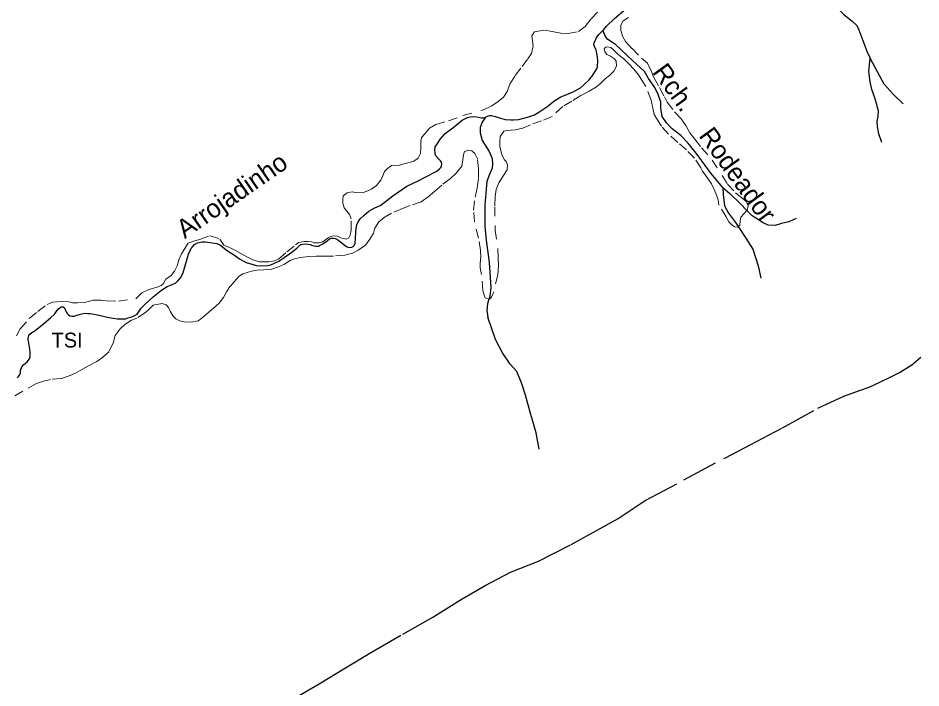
# Model space of a CAD drawing. Extents: x 391.8 to 446, y 8452 to 8507.5.
# Drawn here: x 436.28 to 445.98, y 8458.87 to 8466.06 of the extents above; entities that cross this region are included whole.
import ezdxf
from ezdxf.enums import TextEntityAlignment as Align

# ---------------------------------------------------------------- set-up
doc = ezdxf.new("R2010")
doc.units = 0
doc.header["$LTSCALE"] = 0.064
doc.linetypes.add('LONG_DASHED', pattern=[7.5, 6, -1.5])
doc.linetypes.add('SHORT_DASHED', pattern=[2.7, 1.5, -1.2])
for name, color, linetype, lineweight in [('21', 7, 'SHORT_DASHED', 13), ('7', 7, 'Continuous', 25), ('9', 7, 'LONG_DASHED', 25)]:
    doc.layers.add(name, color=color, linetype=linetype, lineweight=lineweight)
doc.layers.add('61', color=7, linetype='Continuous')

msp = doc.modelspace()

# ---------------------------------------------------------------- linework, layer by layer
at = {"layer": '21'}
for points in [[(440.4417, 8464.5019), (440.5309, 8464.5279), (440.5793, 8464.5613), (440.6053, 8464.6096), (440.609, 8464.6727), (440.609, 8464.7358), (440.6164, 8464.7803), (440.6499, 8464.8212), (440.7019, 8464.8806), (440.7696, 8464.9199), (440.9034, 8464.9607), (441.0595, 8465.0164), (441.2826, 8465.0795), (441.3718, 8465.1204), (441.4387, 8465.1686), (441.4944, 8465.2132), (441.5353, 8465.2763), (441.5651, 8465.3542), (441.6208, 8465.447), (441.6952, 8465.5436), (441.7556, 8465.6272), (441.7965, 8465.6829), (441.8151, 8465.7646), (441.8077, 8465.8202), (441.8002, 8465.8722), (441.83, 8465.9168), (441.9378, 8465.9353), (442.0196, 8465.9205), (442.1125, 8465.9019), (442.1905, 8465.8982), (442.3021, 8465.9205), (442.3727, 8465.9724), (442.4359, 8466.0578), (442.5065, 8466.1284)], [(442.8392, 8466.0715), (442.7798, 8466.0344), (442.7575, 8465.9898), (442.7575, 8465.9304), (442.776, 8465.8636), (442.8058, 8465.8116), (442.8764, 8465.7374), (442.9768, 8465.6334), (443.0437, 8465.5815), (443.0808, 8465.4961), (443.1106, 8465.4255), (443.1701, 8465.3179), (443.2258, 8465.2176), (443.2523, 8465.1599), (443.3341, 8465.056), (443.4047, 8464.9817), (443.453, 8464.9112), (443.4976, 8464.8333), (443.5497, 8464.7627), (443.624, 8464.6699), (443.7355, 8464.54), (443.9033, 8464.2814), (443.9888, 8464.1886), (444.0557, 8464.1329), (444.1041, 8464.092), (444.1226, 8464.0475), (444.1115, 8463.9992), (444.1104, 8463.998)], [(444.016, 8463.8247), (444.0074, 8463.8173), (443.9777, 8463.821), (443.9517, 8463.8396), (443.9145, 8463.8767), (443.8885, 8463.9287), (443.81, 8464.0563), (443.8025, 8464.112), (443.7802, 8464.1751), (443.7579, 8464.2233), (443.7282, 8464.2827), (443.691, 8464.3421), (443.6315, 8464.4201), (443.6166, 8464.4551), (443.546, 8464.5591), (443.4605, 8464.6482), (443.3676, 8464.7298), (443.2672, 8464.8189), (443.1929, 8464.9043), (443.152, 8464.9637), (443.1148, 8465.0305), (443.0999, 8465.0973), (443.0813, 8465.1827), (443.0245, 8465.3293), (442.9911, 8465.3813), (442.9465, 8465.4555), (442.8944, 8465.5149), (442.8461, 8465.5706), (442.7866, 8465.6263), (442.7271, 8465.6746), (442.6788, 8465.7228), (442.6491, 8465.7488), (442.6119, 8465.7563), (442.5933, 8465.7525), (442.5784, 8465.7377), (442.5859, 8465.7043), (442.6045, 8465.6746), (442.6454, 8465.656), (442.6895, 8465.6258), (442.7044, 8465.5998), (442.7081, 8465.5479), (442.6821, 8465.4959), (442.6338, 8465.4476), (442.5892, 8465.4105), (442.5409, 8465.3659), (442.4962, 8465.3251), (442.4145, 8465.2806), (442.3253, 8465.2323), (442.2286, 8465.1729), (442.132, 8465.1135), (442.0188, 8465.0078), (441.9036, 8464.9595), (441.7847, 8464.9187), (441.7029, 8464.8815), (441.6211, 8464.863), (441.5356, 8464.8555), (441.4984, 8464.8481), (441.4613, 8464.7924), (441.4575, 8464.7368), (441.4575, 8464.6848), (441.4761, 8464.5957), (441.5059, 8464.5416), (441.5245, 8464.5231), (441.5394, 8464.4897), (441.5357, 8464.434), (441.4873, 8464.3634), (441.4464, 8464.2966), (441.4167, 8464.2224), (441.4055, 8464.1481), (441.4018, 8464.0368), (441.4055, 8463.788), (441.4351, 8463.5886), (441.4388, 8463.4921), (441.4426, 8463.403), (441.4351, 8463.3065), (441.3905, 8463.1246), (441.3682, 8463.0689), (441.3496, 8463.0503), (441.3381, 8463.0474)], [(441.3381, 8463.0474), (441.3348, 8463.0466), (441.2976, 8463.0615), (441.2864, 8463.0874), (441.2753, 8463.1394), (441.2605, 8463.3121), (441.2456, 8463.3826), (441.2456, 8463.4309), (441.2531, 8463.5014), (441.2494, 8463.5682), (441.2271, 8463.7019), (441.1825, 8463.8764), (441.175, 8464.0026), (441.1898, 8464.1421), (441.2121, 8464.2423), (441.227, 8464.35), (441.227, 8464.4465), (441.2158, 8464.5542), (441.1861, 8464.6099), (441.1563, 8464.6396), (441.1192, 8464.647), (441.0783, 8464.6321), (441.0671, 8464.595), (441.0597, 8464.543), (441.0477, 8464.4755), (440.9882, 8464.3975), (440.925, 8464.3418), (440.8321, 8464.2713), (440.7578, 8464.2045), (440.6871, 8464.1451), (440.6128, 8464.0894), (440.4938, 8464.0522), (440.4121, 8464.0188), (440.2931, 8463.9706), (440.2262, 8463.9297), (440.158, 8463.8763), (440.1134, 8463.8094), (440.0985, 8463.7537), (440.0614, 8463.6906), (440.013, 8463.6275), (439.935, 8463.5718), (439.8755, 8463.5384), (439.79, 8463.5199)], [(440.1778, 8464.3237), (440.2001, 8464.372), (440.2187, 8464.4165), (440.2484, 8464.4499), (440.293, 8464.4796), (440.3748, 8464.4834), (440.4417, 8464.5019)], [(436.2643, 8462.6516), (436.3052, 8462.7258), (436.4019, 8462.8372), (436.4925, 8462.9134), (436.5929, 8462.9876), (436.6523, 8463.0136), (436.7453, 8463.021), (436.827, 8463.0173), (436.8679, 8463.0062), (436.92, 8463.0062), (436.9943, 8463.0099), (437.0872, 8463.0359), (437.1727, 8463.0359), (437.2322, 8463.0284), (437.3586, 8463.0247), (437.5482, 8463.0507), (437.5779, 8463.0804), (437.6114, 8463.1138), (437.6857, 8463.1509), (437.7749, 8463.1732), (437.8178, 8463.1934), (437.8438, 8463.2157), (437.8698, 8463.2602), (437.9256, 8463.3011), (437.9627, 8463.3456), (437.9888, 8463.405), (438.0074, 8463.4681), (438.0371, 8463.5312), (438.0853, 8463.6091), (438.1091, 8463.6485), (438.1648, 8463.6671), (438.2343, 8463.6849), (438.3412, 8463.7265), (438.4489, 8463.6915), (438.4904, 8463.624), (438.5462, 8463.6054), (438.6168, 8463.5683), (438.6726, 8463.5349), (438.7395, 8463.5015), (438.8027, 8463.4681), (438.8733, 8463.4458), (438.9737, 8463.4458), (439.0369, 8463.4569), (439.0815, 8463.4792), (439.167, 8463.5534), (439.262, 8463.628), (439.2955, 8463.6539), (439.355, 8463.6651), (439.3959, 8463.6651), (439.4368, 8463.6614), (439.4628, 8463.6502), (439.5148, 8463.6502), (439.5557, 8463.6614), (439.5854, 8463.6836), (439.6115, 8463.7059), (439.6375, 8463.717), (439.6709, 8463.7245), (439.7118, 8463.7208), (439.7416, 8463.7096), (439.7602, 8463.7022), (439.8048, 8463.6911), (439.8345, 8463.7059), (439.8494, 8463.7319), (439.8605, 8463.7876), (439.8605, 8463.9101), (439.8419, 8463.9546), (439.7825, 8464.0252), (439.7713, 8464.0771), (439.7713, 8464.1143), (439.775, 8464.1551), (439.8159, 8464.1885), (439.8717, 8464.1997), (439.9274, 8464.1885), (439.9882, 8464.1901), (440.0217, 8464.2012), (440.0774, 8464.2272), (440.1332, 8464.268), (440.1778, 8464.3237)], [(444.1104, 8463.998), (444.078, 8463.9621), (444.0446, 8463.925), (444.0372, 8463.8879), (444.0334, 8463.8396), (444.016, 8463.8247)], [(439.79, 8463.5199), (439.6711, 8463.5087), (439.5781, 8463.5087), (439.4852, 8463.5087), (439.4034, 8463.505), (439.3142, 8463.4939), (439.251, 8463.479), (439.2027, 8463.4605), (439.1432, 8463.4233), (439.08, 8463.3937), (438.9961, 8463.3659), (438.9217, 8463.3621), (438.8511, 8463.3584), (438.7879, 8463.3473), (438.695, 8463.3176), (438.6578, 8463.2916), (438.6243, 8463.2582), (438.5574, 8463.1802), (438.5202, 8463.1246), (438.4868, 8463.0652), (438.4385, 8462.9983), (438.379, 8462.9501), (438.3084, 8462.887), (438.2563, 8462.8424), (438.2154, 8462.8127), (438.1411, 8462.7979), (438.0667, 8462.8016), (438.0184, 8462.8127), (437.9775, 8462.835), (437.9478, 8462.8647), (437.9143, 8462.9167), (437.8958, 8462.9575), (437.8735, 8462.9835), (437.8288, 8462.9983), (437.7322, 8462.9798), (437.6876, 8462.9352), (437.6504, 8462.9018), (437.556, 8462.841), (437.5002, 8462.8188), (437.4296, 8462.7742), (437.3775, 8462.726), (437.3255, 8462.6554), (437.3032, 8462.5738), (437.2549, 8462.4809), (437.188, 8462.4178), (437.1285, 8462.377), (437.0467, 8462.3324), (436.9724, 8462.2953), (436.898, 8462.2508), (436.8423, 8462.2248), (436.7456, 8462.1951), (436.6304, 8462.184), (436.556, 8462.1654), (436.478, 8462.1394), (436.3317, 8462.059), (436.2239, 8461.9922)]]:
    msp.add_lwpolyline(points, dxfattribs=at)
at = {"layer": '7'}
for points in [[(442.5638, 8465.9316), (442.5723, 8465.9401), (442.6018, 8465.976), (442.6893, 8466.0586), (442.8046, 8466.1584)], [(441.3012, 8465), (441.3109, 8465.0049), (441.3237, 8465.0126), (441.3493, 8465.0177), (441.3685, 8465.0177), (441.4108, 8465.0062), (441.4647, 8464.9883), (441.5121, 8464.9755), (441.5736, 8464.9703), (441.6044, 8464.9716), (441.662, 8464.9767), (441.7552, 8464.9998), (441.8282, 8465.0254), (441.8872, 8465.06), (441.9602, 8465.1099), (442.0474, 8465.1777), (442.1118, 8465.2182), (442.1926, 8465.2502), (442.2502, 8465.2758), (442.322, 8465.3142), (442.3605, 8465.3501), (442.4143, 8465.4025), (442.454, 8465.4499), (442.4827, 8465.4991), (442.5007, 8465.5247), (442.5045, 8465.5426), (442.5083, 8465.6002), (442.5045, 8465.6437), (442.4981, 8465.6847), (442.4917, 8465.7218), (442.475, 8465.75), (442.4672, 8465.7814), (442.4711, 8465.8006), (442.4826, 8465.8288), (442.4954, 8465.8544), (442.5185, 8465.8864), (442.5638, 8465.9316)], [(443.8518, 8464.2449), (443.7209, 8464.3995), (443.6249, 8464.533), (443.5535, 8464.6281), (443.4741, 8464.7232), (443.3987, 8464.8024), (443.3075, 8464.8738), (443.248, 8464.9411), (443.2004, 8465.0085), (443.1845, 8465.0956), (443.1845, 8465.163), (443.1567, 8465.2422), (443.121, 8465.3175), (443.0536, 8465.4166), (443.0096, 8465.4904), (442.8827, 8465.6093), (442.7002, 8465.7797), (442.6168, 8465.8351), (442.593, 8465.8668), (442.5638, 8465.9316)], [(438.1514, 8463.6048), (438.1765, 8463.632), (438.2105, 8463.6523), (438.2581, 8463.662), (438.2895, 8463.6599), (438.4177, 8463.6426), (438.4571, 8463.627), (438.4974, 8463.5894), (438.5295, 8463.5638), (438.6164, 8463.5115), (438.6612, 8463.4782), (438.7099, 8463.4513), (438.733, 8463.4385), (438.7676, 8463.4283), (438.806, 8463.4168), (438.8406, 8463.4078), (438.888, 8463.4052), (438.9624, 8463.4078), (438.9957, 8463.4155), (439.0815, 8463.4526), (439.1969, 8463.5319), (439.2761, 8463.5937), (439.3082, 8463.6269), (439.3197, 8463.6333), (439.3351, 8463.6359), (439.3709, 8463.6385), (439.3991, 8463.6372), (439.4184, 8463.6321), (439.435, 8463.6257), (439.4568, 8463.618), (439.4786, 8463.6141), (439.5068, 8463.6167), (439.5209, 8463.6218), (439.5568, 8463.641), (439.6003, 8463.6717), (439.626, 8463.6935), (439.6452, 8463.6999), (439.6708, 8463.7012), (439.6875, 8463.6961), (439.7041, 8463.6897), (439.7272, 8463.6756), (439.7836, 8463.6282), (439.8092, 8463.6103), (439.8246, 8463.6039), (439.8451, 8463.6013), (439.8656, 8463.6026), (439.8797, 8463.6116), (439.89, 8463.6205), (439.9015, 8463.6474), (439.9053, 8463.6986), (439.9105, 8463.7677), (439.913, 8463.8074), (439.9207, 8463.8445), (439.9348, 8463.8778), (439.9553, 8463.9085), (439.9972, 8463.9439), (440.051, 8463.9925), (440.1074, 8464.0245), (440.1766, 8464.0565), (440.3086, 8464.1551), (440.4588, 8464.2582), (440.5716, 8464.312), (440.6549, 8464.3568), (440.7809, 8464.4211), (440.8091, 8464.4467), (440.8232, 8464.4608), (440.8296, 8464.4774), (440.8335, 8464.4966), (440.8296, 8464.5158), (440.8207, 8464.5312), (440.8002, 8464.5504), (440.7681, 8464.5862), (440.763, 8464.6016), (440.7604, 8464.6208), (440.7566, 8464.6425), (440.763, 8464.6808), (440.7861, 8464.7192), (440.8207, 8464.7691), (440.8706, 8464.8242), (440.9501, 8464.8843), (441.0526, 8464.9675), (441.0815, 8464.9831), (441.1084, 8464.9959), (441.1404, 8465.0049), (441.1763, 8465.0075), (441.2045, 8465.0036), (441.2276, 8464.9985), (441.2609, 8464.9934), (441.2801, 8464.9934), (441.2955, 8464.9972), (441.3012, 8465)], [(441.3012, 8465), (441.2652, 8464.946), (441.2462, 8464.8893), (441.2462, 8464.8326), (441.2652, 8464.7506), (441.3409, 8464.6308), (441.3725, 8464.5552), (441.3788, 8464.4985), (441.3725, 8464.4543), (441.3409, 8464.3787), (441.3157, 8464.3094), (441.3096, 8464.2268), (441.2969, 8464.0566), (441.2969, 8463.8296), (441.3096, 8463.6783), (441.3411, 8463.4388), (441.36, 8463.1718), (441.3473, 8463.0773), (441.3381, 8463.0474)], [(443.8518, 8464.2449), (443.9272, 8464.1815), (444.0383, 8464.0745), (444.1104, 8463.998), (444.1653, 8463.9398)], [(438.0412, 8463.2991), (438.0541, 8463.3311), (438.0656, 8463.3695), (438.1117, 8463.5293), (438.1335, 8463.5754), (438.1425, 8463.5946), (438.1514, 8463.6048)], [(436.2712, 8462.2007), (436.2853, 8462.2147), (436.2968, 8462.2314), (436.307, 8462.2531), (436.3083, 8462.2787), (436.3228, 8462.3204), (436.3433, 8462.346), (436.3779, 8462.3716), (436.4048, 8462.4049), (436.4112, 8462.4292), (436.4125, 8462.465), (436.4086, 8462.5124), (436.4009, 8462.5521), (436.391, 8462.6156), (436.3922, 8462.6399), (436.3986, 8462.654), (436.4076, 8462.6693), (436.4307, 8462.6872), (436.4653, 8462.709), (436.5576, 8462.7832), (436.6308, 8462.8454), (436.6757, 8462.8876), (436.6975, 8462.9196), (436.7129, 8462.9388), (436.7321, 8462.9567), (436.7436, 8462.9619), (436.7654, 8462.9619), (436.7795, 8462.9542), (436.7846, 8462.9452), (436.7885, 8462.935), (436.7974, 8462.9107), (436.8077, 8462.8927), (436.8244, 8462.8761), (436.841, 8462.8684), (436.859, 8462.8633), (436.8718, 8462.8633), (436.8859, 8462.8646), (436.9025, 8462.8697), (436.9128, 8462.8723), (436.9307, 8462.8787), (436.9384, 8462.8812), (436.9679, 8462.8876), (436.9986, 8462.894), (437.0307, 8462.8927), (437.0576, 8462.8902), (437.1343, 8462.8761), (437.2407, 8462.8518), (437.3035, 8462.8415), (437.3509, 8462.8364), (437.3906, 8462.8339), (437.4342, 8462.8364), (437.4624, 8462.8441), (437.5136, 8462.8595), (437.561, 8462.8838), (437.5828, 8462.9158), (437.6021, 8462.949), (437.6418, 8462.9887), (437.7328, 8463.0706), (437.8234, 8463.1417), (437.8836, 8463.1814), (437.9708, 8463.2185), (438.0028, 8463.2466), (438.0246, 8463.2735), (438.0412, 8463.2991)], [(441.3381, 8463.0474), (441.3221, 8462.9953), (441.3158, 8462.926), (441.3283, 8462.8538)]]:
    msp.add_lwpolyline(points, dxfattribs=at)
at = {"layer": '9'}
for points in [[(444.907, 8466.5788), (444.9293, 8466.535), (444.9796, 8466.4857), (445.0225, 8466.3879), (445.0736, 8466.2343), (445.0906, 8466.1864), (445.1056, 8466.149), (445.1522, 8466.1021), (445.2405, 8466.0307), (445.291, 8465.9845), (445.3108, 8465.9394), (445.3976, 8465.7081), (445.4355, 8465.6353)], [(445.5601, 8464.7277), (445.5265, 8464.8201), (445.5139, 8464.8957), (445.5097, 8464.9587), (445.5184, 8465.0085), (445.5243, 8465.0693), (445.5105, 8465.1154), (445.5055, 8465.135), (445.4845, 8465.2064), (445.4508, 8465.2988), (445.434, 8465.3786), (445.4214, 8465.492), (445.4355, 8465.6353)], [(445.7885, 8465.1442), (445.6799, 8465.2454), (445.5858, 8465.3539), (445.4917, 8465.5274), (445.4355, 8465.6353)], [(443.8518, 8464.2449), (443.8558, 8464.1696), (443.8677, 8464.0468), (443.9114, 8463.9676), (443.9867, 8463.8685), (444.016, 8463.8247)], [(444.6394, 8463.9133), (444.562, 8463.8764), (444.4827, 8463.8566), (444.4152, 8463.8368), (444.3398, 8463.8408), (444.2843, 8463.8645), (444.1653, 8463.9398)], [(444.016, 8463.8247), (444.0978, 8463.7021), (444.1732, 8463.5832), (444.2327, 8463.4049), (444.2605, 8463.2702)], [(441.8775, 8461.4355), (441.8459, 8461.612), (441.7828, 8461.8326), (441.7323, 8462.0154), (441.6881, 8462.1478), (441.6376, 8462.2675), (441.5682, 8462.3495), (441.4861, 8462.4693), (441.4104, 8462.6142), (441.3283, 8462.8538)], [(439.2077, 8458.7363), (439.5154, 8458.9165), (439.7984, 8459.0885), (440.0609, 8459.2442), (440.4136, 8459.449), (440.735, 8459.6323), (441.0508, 8459.828), (441.3051, 8459.9755), (441.5717, 8460.1148), (441.8711, 8460.2336), (442.222, 8460.4114), (442.5337, 8460.5834), (442.7265, 8460.6899), (442.8782, 8460.7923), (443.0177, 8460.8824), (443.4343, 8461.1065), (443.8803, 8461.3436), (444.1438, 8461.4834), (444.4925, 8461.6636), (444.871, 8461.8745), (445.1499, 8462.0055), (445.3191, 8462.0634), (445.4217, 8462.1002), (445.5447, 8462.1576), (445.6473, 8462.2067), (445.7498, 8462.26), (445.881, 8462.3419), (445.9795, 8462.4238)]]:
    msp.add_lwpolyline(points, dxfattribs=at)

# ---------------------------------------------------------------- texts
at = {"layer": '61'}
for s, rotation, p in [('Rch.    Rodeador', 306.057, (443.6826, 8464.6667)), ('Rio                                                           Arrojadinho', 34.698, (436.6675, 8462.7175))]:
    msp.add_text(s, height=0.2, rotation=rotation, dxfattribs=at).set_placement(p, align=Align.CENTER)
msp.add_text('TSI', height=0.16, dxfattribs=at).set_placement((436.8086, 8462.5263), align=Align.CENTER)

doc.saveas('drawing.dxf')
